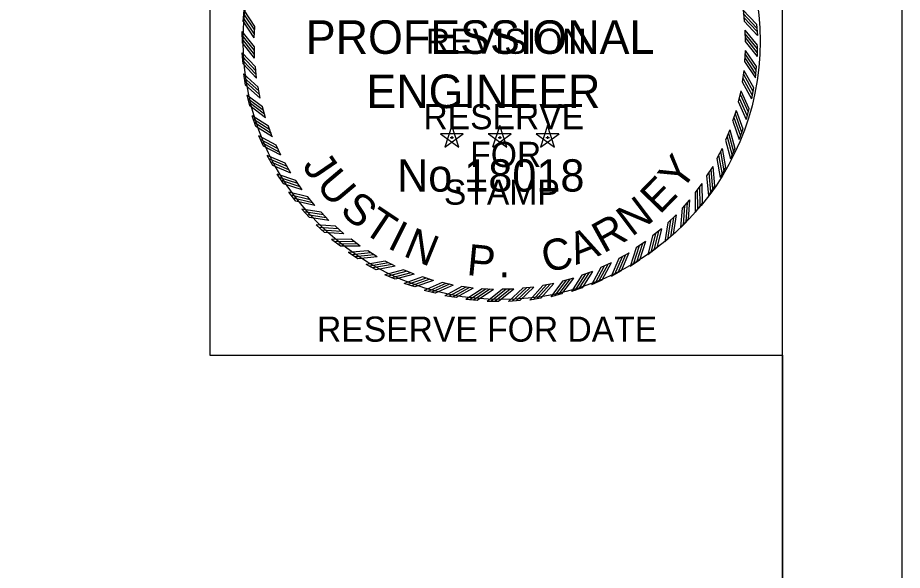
# Model space of a CAD drawing. Extents: x 0 to 1228743, y 0 to 152440.
# Drawn here: x 29.741 to 34, y 16.545 to 19.207 of the extents above; entities that cross this region are included whole.
import ezdxf

# ---------------------------------------------------------------- set-up
doc = ezdxf.new("R2010")
doc.units = 0
for name, color, linetype in [('R_Border', 7, 'Continuous'), ('R_Draft', 7, 'Continuous'), ('R_No Plot', 7, 'Continuous'), ('STAMP_JUSTIN', 7, 'Continuous')]:
    doc.layers.add(name, color=color, linetype=linetype)

msp = doc.modelspace()

# ---------------------------------------------------------------- linework, layer by layer
at = {"layer": 'R_Border'}
msp.add_line((33.4232, 0.5768), (33.4232, 21.4232), dxfattribs=at)
msp.add_lwpolyline([(34, 22), (0, 22), (0, 0), (34, 0)], close=True, dxfattribs=at)
at = {"layer": 'R_Draft'}
msp.add_circle((32.0709, 19.0937), 1.2447, dxfattribs=at)
at = {"layer": 'R_No Plot'}
for points in [[(33.4232, 17.5816), (33.4232, 10.8708), (1.516, 10.8708), (1.516, 21.4232), (25.1972, 21.4232), (27.1592, 21.4232), (27.1592, 20.4352), (28.7492, 20.4352), (30.6666, 20.4352)], [(30.6666, 20.4352), (30.6666, 17.5816), (33.4232, 17.5816)]]:
    msp.add_lwpolyline(points, dxfattribs=at)
at = {"layer": 'STAMP_JUSTIN'}
for p, q in [((30.8272, 19.1888), (30.8312, 19.243)), ((33.233, 19.2448), (33.238, 19.1905)), ((33.2974, 19.1762), (33.3023, 19.1221)), ((30.8225, 19.0865), (30.822, 19.1409)), ((30.8794, 19.1106), (30.8834, 19.165)), ((33.2426, 19.1475), (33.2431, 19.093)), ((30.8262, 18.9842), (30.8212, 19.0383)), ((30.881, 19.0129), (30.8805, 19.0674)), ((33.2441, 19.0498), (33.2401, 18.9954)), ((33.3011, 19.0739), (33.3016, 19.0195)), ((30.8905, 18.9156), (30.8855, 18.9699)), ((33.2963, 18.9716), (33.2923, 18.9174)), ((30.8383, 18.8825), (30.8289, 18.936)), ((33.2375, 18.9522), (33.2291, 18.8984)), ((30.9081, 18.8195), (30.8987, 18.8731)), ((33.2831, 18.87), (33.2747, 18.8163)), ((30.8588, 18.7821), (30.845, 18.8347)), ((33.2229, 18.8556), (33.2101, 18.8026)), ((30.9336, 18.7251), (30.9198, 18.7778)), ((33.2004, 18.7604), (33.1832, 18.7088)), ((33.2616, 18.7698), (33.2487, 18.717)), ((30.8875, 18.6838), (30.8694, 18.735)), ((30.9668, 18.6331), (30.9486, 18.6845)), ((31.8312, 18.6882), (31.7972, 18.5839)), ((31.865, 18.5839), (31.8312, 18.6883)), ((32.0617, 18.6882), (32.0277, 18.5839)), ((32.0955, 18.5839), (32.0617, 18.6883)), ((32.2921, 18.6882), (32.2581, 18.5839)), ((32.326, 18.5839), (32.2922, 18.6883)), ((33.1701, 18.6675), (33.1487, 18.6174)), ((33.2319, 18.6718), (33.2147, 18.6203)), ((30.9243, 18.5882), (30.902, 18.6377)), ((31.886, 18.6484), (31.7763, 18.6485)), ((31.7764, 18.6484), (31.865, 18.5838)), ((31.7973, 18.5839), (31.8861, 18.6483)), ((31.8234, 18.6308), (31.8397, 18.6308)), ((31.8313, 18.6367), (31.8313, 18.6229)), ((32.1165, 18.6484), (32.0068, 18.6485)), ((32.0069, 18.6484), (32.0955, 18.5838)), ((32.0278, 18.5839), (32.1166, 18.6483)), ((32.0538, 18.6308), (32.0701, 18.6308)), ((32.0618, 18.6367), (32.0618, 18.6229)), ((32.3469, 18.6484), (32.2372, 18.6485)), ((32.2373, 18.6484), (32.326, 18.5838)), ((32.2583, 18.5839), (32.3471, 18.6483)), ((32.2843, 18.6308), (32.3006, 18.6308)), ((32.2922, 18.6367), (32.2922, 18.6229)), ((31.0074, 18.5443), (30.9851, 18.5939)), ((33.1323, 18.5774), (33.1068, 18.5292)), ((33.1941, 18.5766), (33.1728, 18.5266)), ((30.9688, 18.4959), (30.9425, 18.5435)), ((31.0553, 18.459), (31.0289, 18.5067)), ((33.0871, 18.4907), (33.0577, 18.4448)), ((33.1487, 18.4848), (33.1233, 18.4368)), ((31.0208, 18.4077), (30.9907, 18.4529)), ((31.11, 18.378), (31.0798, 18.4233)), ((33.0349, 18.408), (33.0019, 18.3648)), ((31.0799, 18.324), (31.0461, 18.3666)), ((33.0958, 18.3971), (33.0665, 18.3513)), ((31.1713, 18.3018), (31.1374, 18.3445)), ((32.9761, 18.33), (32.9396, 18.2896)), ((31.1457, 18.2455), (31.1085, 18.2851)), ((33.0359, 18.314), (33.0029, 18.2708)), ((31.2386, 18.231), (31.2013, 18.2707)), ((32.911, 18.257), (32.8713, 18.2198)), ((32.9693, 18.2362), (32.9328, 18.1959)), ((31.2177, 18.1727), (31.1774, 18.2091)), ((31.3115, 18.1659), (31.2711, 18.2024)), ((32.8401, 18.1897), (32.7975, 18.1559)), ((32.8965, 18.1641), (32.8568, 18.127)), ((31.2956, 18.1061), (31.2524, 18.1391)), ((31.3896, 18.1071), (31.3463, 18.1401)), ((32.7639, 18.1285), (32.7186, 18.0983)), ((31.3786, 18.0462), (31.3329, 18.0755)), ((31.4723, 18.0549), (31.4264, 18.0842)), ((32.6829, 18.0737), (32.6353, 18.0474)), ((32.818, 18.0983), (32.7754, 18.0646)), ((31.4664, 17.9933), (31.4183, 18.0187)), ((31.5589, 18.0097), (31.5108, 18.0352)), ((32.5977, 18.0259), (32.548, 18.0035)), ((32.7343, 18.0392), (32.6891, 18.0091)), ((31.6491, 17.9718), (31.599, 17.9932)), ((32.5088, 17.9852), (32.4575, 17.9671)), ((32.646, 17.9873), (32.5985, 17.961)), ((31.5581, 17.9478), (31.5082, 17.9692)), ((31.742, 17.9415), (31.6903, 17.9587)), ((31.8371, 17.919), (31.7842, 17.9319)), ((32.4169, 17.9521), (32.3642, 17.9382)), ((32.5538, 17.9427), (32.5042, 17.9205)), ((31.6534, 17.9101), (31.6018, 17.9273)), ((31.7514, 17.8804), (31.6986, 17.8932)), ((31.9338, 17.9044), (31.88, 17.9129)), ((32.0313, 17.8979), (31.977, 17.9019)), ((32.129, 17.8994), (32.0746, 17.8989)), ((32.2263, 17.909), (32.1721, 17.904)), ((32.3225, 17.9266), (32.2688, 17.9171)), ((32.4582, 17.906), (32.4069, 17.8879)), ((31.8515, 17.8588), (31.7979, 17.8673)), ((31.9531, 17.8457), (31.8989, 17.8496)), ((32.2595, 17.8568), (32.206, 17.8473)), ((32.3599, 17.8773), (32.3073, 17.8634)), ((32.0554, 17.8409), (32.0011, 17.8404)), ((32.1578, 17.8446), (32.1037, 17.8396))]:
    msp.add_line(p, q, dxfattribs=at)
for points in [[(30.8819, 19.1469), (30.8297, 19.225)], [(30.8834, 19.1649), (30.8312, 19.2431)], [(33.2329, 19.2448), (33.2973, 19.1763)], [(33.2344, 19.2274), (33.2987, 19.1589)], [(33.2365, 19.2086), (33.3009, 19.1401)], [(30.8795, 19.1106), (30.8273, 19.1888)], [(30.8809, 19.128), (30.8287, 19.2062)], [(33.238, 19.1906), (33.3024, 19.1221)], [(30.8804, 19.0673), (30.8219, 19.1409)], [(33.2425, 19.1476), (33.301, 19.074)], [(33.2425, 19.1301), (33.301, 19.0565)], [(30.8804, 19.0492), (30.8219, 19.1228)], [(30.881, 19.0303), (30.8225, 19.1039)], [(30.881, 19.0128), (30.8225, 19.0864)], [(33.2431, 19.1112), (33.3016, 19.0376)], [(33.2431, 19.0931), (33.3016, 19.0195)], [(30.8855, 18.9698), (30.8211, 19.0383)], [(33.244, 19.0498), (33.2963, 18.9716)], [(30.887, 18.9518), (30.8226, 19.0203)], [(30.8892, 18.933), (30.8248, 19.0015)], [(33.2416, 19.0135), (33.2938, 18.9354)], [(33.2426, 19.0324), (33.2948, 18.9542)], [(30.8906, 18.9156), (30.8262, 18.9841)], [(33.2401, 18.9955), (33.2924, 18.9173)], [(30.8986, 18.873), (30.8288, 18.936)], [(30.9016, 18.8552), (30.8318, 18.9182)], [(33.2321, 18.9163), (33.2777, 18.8341)], [(33.2346, 18.935), (33.2802, 18.8528)], [(33.2375, 18.9523), (33.2831, 18.8701)], [(30.9053, 18.8367), (30.8355, 18.8996)], [(30.9082, 18.8194), (30.8384, 18.8824)], [(33.2291, 18.8985), (33.2747, 18.8162)], [(30.9197, 18.7777), (30.8449, 18.8347)], [(33.2186, 18.8387), (33.2573, 18.753)], [(33.2229, 18.8556), (33.2616, 18.7699)], [(30.9242, 18.7601), (30.8494, 18.8171)], [(30.9294, 18.742), (30.8546, 18.799)], [(33.2101, 18.8027), (33.2488, 18.717)], [(33.2146, 18.8202), (33.2532, 18.7345)], [(30.9337, 18.725), (30.8589, 18.782)], [(33.1947, 18.744), (33.2262, 18.6554)], [(33.2004, 18.7605), (33.2318, 18.6719)], [(30.9486, 18.6844), (30.8694, 18.735)], [(30.9545, 18.6673), (30.8753, 18.7179)], [(30.9612, 18.6496), (30.8819, 18.7003)], [(33.1833, 18.7088), (33.2147, 18.6202)], [(33.1892, 18.7259), (33.2206, 18.6373)], [(30.9669, 18.6331), (30.8876, 18.6837)], [(33.1701, 18.6676), (33.1941, 18.5767)], [(30.9851, 18.5939), (30.902, 18.6378)], [(30.9924, 18.5773), (30.9092, 18.6212)], [(33.1488, 18.6175), (33.1728, 18.5266)], [(33.156, 18.634), (33.1801, 18.5431)], [(33.1631, 18.6516), (33.1871, 18.5607)], [(31.0005, 18.5602), (30.9173, 18.6041)], [(31.0075, 18.5442), (30.9244, 18.5881)], [(33.1323, 18.5775), (33.1487, 18.4849)], [(31.0289, 18.5066), (30.9425, 18.5435)], [(31.0376, 18.4907), (30.9511, 18.5276)], [(33.1069, 18.5293), (33.1233, 18.4367)], [(33.1155, 18.5452), (33.1319, 18.4526)], [(33.1239, 18.5621), (33.1403, 18.4695)], [(31.0471, 18.4744), (30.9606, 18.5113)], [(31.0554, 18.459), (30.9689, 18.4959)], [(33.0871, 18.4908), (33.0958, 18.3972)], [(31.0798, 18.4233), (30.9906, 18.4529)], [(33.0578, 18.4449), (33.0665, 18.3512)], [(33.0677, 18.46), (33.0764, 18.3664)], [(33.0775, 18.4761), (33.0862, 18.3825)], [(31.0897, 18.4081), (31.0005, 18.4377)], [(31.1005, 18.3926), (31.0113, 18.4223)], [(31.1101, 18.378), (31.0209, 18.4076)], [(33.0349, 18.4081), (33.0359, 18.3141)], [(31.1374, 18.3444), (31.0461, 18.3666)], [(33.0019, 18.3648), (33.0029, 18.2708)], [(33.013, 18.3791), (33.014, 18.2851)], [(33.0242, 18.3943), (33.0251, 18.3003)], [(31.1486, 18.3301), (31.0572, 18.3523)], [(31.1606, 18.3156), (31.0692, 18.3378)], [(31.1714, 18.3018), (31.08, 18.324)], [(32.9642, 18.3172), (32.9574, 18.2234)], [(32.9761, 18.3301), (32.9693, 18.2363)], [(31.2013, 18.2706), (31.1085, 18.2851)], [(31.2136, 18.2573), (31.1207, 18.2718)], [(32.9396, 18.2896), (32.9328, 18.1958)], [(32.9519, 18.3029), (32.9451, 18.2091)], [(31.2268, 18.2438), (31.1339, 18.2583)], [(31.2387, 18.2309), (31.1458, 18.2455)], [(32.8847, 18.2321), (32.8701, 18.1392)], [(32.8981, 18.2453), (32.8836, 18.1524)], [(32.911, 18.2571), (32.8965, 18.1642)], [(31.2711, 18.2023), (31.1774, 18.2091)], [(31.2845, 18.1901), (31.1907, 18.1969)], [(32.8401, 18.1898), (32.818, 18.0984)], [(32.8713, 18.2198), (32.8568, 18.1269)], [(31.2987, 18.1777), (31.205, 18.1845)], [(31.3116, 18.1659), (31.2178, 18.1727)], [(32.7975, 18.1559), (32.7754, 18.0645)], [(32.8118, 18.167), (32.7897, 18.0756)], [(32.8263, 18.1791), (32.8042, 18.0877)], [(31.3463, 18.14), (31.2523, 18.1391)], [(31.3606, 18.1289), (31.2666, 18.128)], [(31.3759, 18.1178), (31.2819, 18.1168)], [(31.3897, 18.1071), (31.2957, 18.1061)], [(32.7338, 18.1082), (32.7042, 18.0189)], [(32.7493, 18.119), (32.7197, 18.0298)], [(32.764, 18.1286), (32.7343, 18.0393)], [(31.4264, 18.0842), (31.3328, 18.0755)], [(31.4416, 18.0743), (31.348, 18.0655)], [(31.4577, 18.0644), (31.3641, 18.0557)], [(32.6676, 18.0655), (32.6307, 17.979)], [(32.683, 18.0738), (32.6461, 17.9873)], [(32.7187, 18.0983), (32.6891, 18.009)], [(31.4723, 18.0549), (31.3787, 18.0462)], [(31.5108, 18.0351), (31.4183, 18.0187)], [(31.5268, 18.0265), (31.4342, 18.0101)], [(31.5436, 18.018), (31.4511, 18.0016)], [(32.5817, 18.0189), (32.5378, 17.9358)], [(32.5977, 18.026), (32.5538, 17.9428)], [(32.6354, 18.0474), (32.5985, 17.9609)], [(32.6513, 18.056), (32.6144, 17.9695)], [(31.559, 18.0097), (31.4664, 17.9933)], [(31.599, 17.9932), (31.5081, 17.9692)], [(31.6156, 17.9859), (31.5247, 17.9619)], [(31.6331, 17.9789), (31.5422, 17.9549)], [(32.4923, 17.9796), (32.4417, 17.9004)], [(32.5089, 17.9853), (32.4582, 17.9061)], [(32.5481, 18.0035), (32.5042, 17.9204)], [(32.5647, 18.0108), (32.5208, 17.9277)], [(31.6491, 17.9718), (31.5582, 17.9478)], [(31.6904, 17.9587), (31.6018, 17.9272)], [(31.7075, 17.9528), (31.6189, 17.9214)], [(31.7255, 17.9472), (31.6369, 17.9158)], [(31.7421, 17.9416), (31.6535, 17.9101)], [(31.7843, 17.9318), (31.6985, 17.8932)], [(32.3643, 17.9382), (32.3073, 17.8634)], [(32.3818, 17.9426), (32.3248, 17.8678)], [(32.4, 17.9478), (32.343, 17.873)], [(32.4169, 17.9521), (32.3599, 17.8773)], [(32.4575, 17.9671), (32.4069, 17.8878)], [(32.4747, 17.9729), (32.424, 17.8937)], [(31.8018, 17.9274), (31.7161, 17.8888)], [(31.8202, 17.9233), (31.7345, 17.8847)], [(31.8372, 17.919), (31.7515, 17.8804)], [(31.88, 17.9128), (31.7978, 17.8673)], [(31.8979, 17.9099), (31.8157, 17.8643)], [(31.9166, 17.9073), (31.8344, 17.8618)], [(31.9339, 17.9045), (31.8516, 17.8589)], [(31.9771, 17.9018), (31.8989, 17.8496)], [(31.9951, 17.9003), (31.9169, 17.8481)], [(32.0139, 17.8994), (31.9358, 17.8471)], [(32.0314, 17.8979), (31.9532, 17.8457)], [(32.0747, 17.8989), (32.001, 17.8404)], [(32.0928, 17.8989), (32.0191, 17.8404)], [(32.1116, 17.8995), (32.038, 17.8409)], [(32.1291, 17.8995), (32.0555, 17.8409)], [(32.1722, 17.904), (32.1036, 17.8396)], [(32.1902, 17.9055), (32.1217, 17.8411)], [(32.209, 17.9076), (32.1404, 17.8432)], [(32.2264, 17.909), (32.1579, 17.8447)], [(32.2689, 17.9171), (32.2059, 17.8473)], [(32.2868, 17.9201), (32.2238, 17.8503)], [(32.3053, 17.9238), (32.2423, 17.8539)], [(32.3225, 17.9266), (32.2596, 17.8568)]]:
    msp.add_lwpolyline(points, dxfattribs=at)

# ---------------------------------------------------------------- texts
at = {"layer": 'R_Draft'}
for s, height, p in [('REVISION', 0.1211, (31.7062, 19.0331)), ('RESERVE', 0.1211, (31.6943, 18.6698)), ('FOR', 0.1211, (31.9198, 18.4882)), ('STAMP', 0.1211, (31.7929, 18.3065)), ('RESERVE FOR DATE', 0.121097, (31.1822, 17.6466))]:
    msp.add_text(s, height=height, dxfattribs=at).set_placement(p)
at = {"layer": 'STAMP_JUSTIN'}
for s, height, p in [('PROFESSIONAL', 0.161342, (31.1279, 19.033)), ('ENGINEER', 0.16134, (31.4198, 18.7718)), ('No.18018', 0.15558, (31.5673, 18.3695))]:
    msp.add_text(s, height=height, dxfattribs=at).set_placement(p)
for s, rotation, p in [('J', 304.3679, (31.1079, 18.4934)), ('Y', 53.4433, (32.935, 18.3653)), ('U', 310.2047, (31.1725, 18.3989)), ('E', 45.7825, (32.8319, 18.256)), ('S', 318.9599, (31.2866, 18.2706)), ('N', 37.0272, (32.6976, 18.1491)), ('T', 326.256, (31.3957, 18.1781)), ('R', 29.0016, (32.5614, 18.0702)), ('I', 333.552, (31.5157, 18.1001)), ('N', 337.9296, (31.5921, 18.0609)), ('C', 14.0448, (32.2841, 17.9768)), ('A', 21.7056, (32.4292, 18.0156)), ('P', 354.3456, (31.8995, 17.9682)), ('.', 2.3712, (32.0563, 17.9557))]:
    msp.add_text(s, height=0.1501, rotation=rotation, dxfattribs=at).set_placement(p)

doc.saveas('drawing.dxf')
